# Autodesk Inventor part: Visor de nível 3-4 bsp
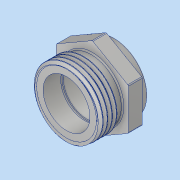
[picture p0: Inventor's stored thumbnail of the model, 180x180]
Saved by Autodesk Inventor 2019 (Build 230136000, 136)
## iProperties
Created: 2019-08
Part Number: Visor de nível 3-4 bsp
Material: Alumínio 6061
Document SubType Name: Modeling
Designer: Usuario
Density: 2.7 g/cm^3
Appearance: Alumínio - Plano
Author: Usuario
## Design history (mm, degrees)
sketch "Esboço1"
  geometry: L1 (9.3, 0)-(13.2, 0); L2 (13.2, 0)-(13.2, -7.25); L3 (13.2, -7.25)-(12, -7.25); L4 (12, -7.25)-(12, -10.25); L5 (12, -10.25)-(14.3, -10.25); L6 (14.3, -10.25)-(14.3, -19.25); L7 (14.3, -19.25)-(9.3, -19.25); L8 (0, 0)-(0, -19.25); L9 (9.3, -7)-(9.8, -7); L10 (9.8, -7)-(9.8, -8); L11 (9.8, -8)-(9.3, -8); L12 (9.3, 0)-(9.3, -7); L13 (9.3, -8)-(9.3, -19.25)
  constraints: 26 end point, 8 perpendicular, 3 vertical, 2 horizontal
  dimensions: "d0" = 13.2 distance of L8.start L1.end; "d1" = 7.25 distance of L1.end L2.end; "d3" = 1.2 distance of L2.end L3.end; "d4" = 3 distance of L3.end L4.end; "d5" = 2.3 distance of L4.end L5.end; "d6" = 9 distance of L5.end L6.end; "d7" = 19.25 distance of L8.start L8.end; "d8" = 0.5 distance of L9.start L9.end; "d9" = 1 distance of L9.end L10.end
revolve "Revolução1" sketch "Esboço1" stored, may be unused: angle "d10" = 90 deg
feature "Rosca1" dims "d11" = 10, "d12" = 0
sketch "Esboço3"
  geometry: L1 (13.2, 0)-(13.2, 7.25); L2 (13.2, 7.25)-(11.855, 7.25); L3 (11.855, 7.25)-(11.855, 0); L4 (11.855, 0)-(13.2, 0); L5 (0, -15.85)-(0, 11.1) reference
  constraints: 8 end point
revolve "Revolução2" sketch "Esboço3" stored, may be unused: angle "d22" = 0 deg
sketch "Esboço4"
  geometry: L1 (13.2, 0)-(13.2, 7.25); L2 (13.2, 7.25)-(11.855, 7.25); L3 (11.855, 7.25)-(11.855, 0); L4 (11.855, 0)-(13.2, 0); L5 (0, -15.85)-(0, 11.1) reference
  constraints: 8 end point
revolve "Revolução3" sketch "Esboço4" stored, may be unused: angle "d23" = 0 deg
sketch "Esboço2"
  geometry: L1 (-1.058, -11.947)-(-0.907, -11.947); L2 (0.151, -13.108)-(0, -13.399); L3 (-1.814, -13.399)-(-1.966, -13.108); L4 (-0.756, -11.947)-(-0.907, -11.656); L5 (-0.907, -11.656)-(-1.058, -11.947); L6 (-1.814, -13.399)-(-1.663, -13.108); L7 (-0.756, -11.947)-(-0.151, -13.108); L8 (-1.966, -13.108)-(-1.663, -13.108); L9 (0.151, -13.108)-(-0.151, -13.108); L10 (-1.814, -13.399)-(-1.814, -13.108); L11 (0, -13.399)-(0, -13.108); L12 (-0.907, -11.656)-(-0.907, -11.855); L13 (-1.814, -13.2)-(0, -13.2); L14 (-0.151, -13.108)-(0, -13.399); L15 (-1.663, -13.108)-(-1.058, -11.947); L16 (0, 0)-(0, 0.018); L17 (0, 0.018)-(0, 0); L18 (0, 0)-(0.033, 0); L19 (-0.907, -11.855)-(-0.907, -11.947); L20 (-0.907, -11.947)-(-0.756, -11.947); A1 r 0.17 centre (-1.814, -13.03) between (-1.966, -13.108) and (-1.814, -13.2); A2 r 0.17 centre (-1.814, -13.03) between (-1.814, -13.2) and (-1.663, -13.108); A3 r 0.17 centre (0, -13.03) between (-0.151, -13.108) and (0, -13.2); A4 r 0.17 centre (0, -13.03) between (0, -13.2) and (0.151, -13.108); A5 r 0.17 centre (-0.907, -12.025) between (-0.907, -11.855) and (-1.058, -11.947); A6 r 0.17 centre (-0.907, -12.025) between (-0.756, -11.947) and (-0.907, -11.855)
  constraints: 40 end point, 12 point on circle, 10 parallel, 8 tangent, 6 centre point, 6 collinear, 2 midpoint, 2 point on line, 1 horizontal, 1 perpendicular, 3 other
  dimensions: "d13" = 55 deg angle of L7 L15 (= d20); "d14" = 0.29044 distance of L4.end L1.end (= 0.160083 x Esboço2_Pitch); "d15" = 0.29044 distance of L2.end L11.end (= 0.160083 x Esboço2_Pitch); "Esboço2_ThreadOffset" = 0 distance between parallel lines of L16 L11; "Esboço2_MajorRadius" = 13.2 distance from line of L13 L16.start; "d18" = 1.81429 distance from line of L2.end L10 (= Esboço2_Pitch); "Esboço2_MinorRadius" = 11.85478 distance edge to line of A6 L18 (derived)
feature "Espiral1" sketch "Esboço2" pitch "d24" = 1.8161; turns "d26" = 1; dims "d25" = 10.87857, "d27" = 0, angle "d28" = 0 deg, angle "d29" = 0 deg, "d30" = 0, "d31" = 0
sketch "Esboço5" dims "d4" = 3
  geometry: L1 (14.3, 8.256)-(0, 16.512); L2 (0, 16.512)-(-14.3, 8.256); L3 (-14.3, 8.256)-(-14.3, -8.256); L4 (-14.3, -8.256)-(0, -16.512); L5 (0, -16.512)-(14.3, -8.256); L6 (14.3, -8.256)-(14.3, 8.256); C1 r 14.3 at (0, 0) reference; 2 further points
  constraints: 12 end point
extrude "Extrusão1" join sketch "Esboço5" distance "d32" = 9; taper "d33" = 0 deg
node "Plano de trabalho1"
sketch "Esboço7"
  geometry: L1 (-19.25, 0)-(-19.25, -14.3) reference; L2 (-19.25, 0)-(-10.25, 0) reference; L3 (-19.25, -13)-(-15.75, -14.3); L4 (-19.25, -13)-(-19.25, -18); L5 (-19.25, -18)-(-15.75, -18); L6 (-15.75, -14.3)-(-15.75, -18); L7 (-23.221, 0)-(4.576, 0) reference; 1 further point
  constraints: 8 end point, 2 perpendicular, 1 point on line, 1 vertical
  dimensions: "d37" = 5 distance of L3.start L4.end
revolve "Revolução4" sketch "Esboço7" stored, may be unused: angle "d39" = 90 deg
fillet "Arredondamento1" dims "d40" = 1
sketch "Esboço8"
  geometry: C1 r 11.5 at (0, 0); C2 r 9.3 at (0, 0) reference; 1 further point
  constraints: 1 centre point, 1 coincident
  dimensions: "d41" = 23 diameter of C1
extrude "Extrusão2" cut sketch "Esboço8" distance "d42" = 4.5; taper "d43" = 0 deg
fillet "Arredondamento2" dims "d44" = 0.25
fillet "Arredondamento3" dims "d45" = 0.5
node "Sólido1"
node "Sólido2"
other parameters: "d20" = 55 deg [user parameter; used in 1 equation term], "Esboço2_Pitch" = 1.81429 [user parameter; used in 3 equation terms], "d34" = 90 deg
